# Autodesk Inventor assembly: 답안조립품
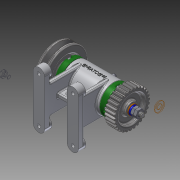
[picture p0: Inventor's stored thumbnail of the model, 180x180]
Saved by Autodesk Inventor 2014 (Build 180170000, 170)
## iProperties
Created: 2015-11
Part Number: 답안조립품
Document SubType Name: Assembly
Designer: Owner
Author: Owner
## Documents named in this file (16)
- C:\Documents and Settings\Owner\바탕 화면\451109V1002\451109V1002\답안조립품.iam
- C:\Documents and Settings\Owner\바탕 화면\451109V1002\451109V1002\본체.ipt
- C:\Documents and Settings\Owner\바탕 화면\451109V1002\451109V1002\축.ipt
- C:\Documents and Settings\Owner\바탕 화면\451109V1002\451109V1002\커버.ipt
- C:\Documents and Settings\Owner\바탕 화면\451109V1002\451109V1002\베어링 15 x 32 x 9.ipt
- C:\Documents and Settings\Owner\바탕 화면\451109V1002\451109V1002\오일 실 15 25 7.ipt
- C:\Documents and Settings\Owner\바탕 화면\451109V1002\451109V1002\V벨트풀리.ipt
- C:\Documents and Settings\Owner\바탕 화면\451109V1002\451109V1002\스퍼기어.ipt
- C:\Documents and Settings\Owner\바탕 화면\451109V1002\451109V1002\키 3 x 3 x 12.ipt
- C:\Documents and Settings\Owner\바탕 화면\451109V1002\451109V1002\볼트 M4 x 12.ipt
- C:\Documents and Settings\Owner\바탕 화면\451109V1002\451109V1002\너트 M 8.ipt
- C:\Documents and Settings\Owner\바탕 화면\451109V1002\451109V1002\스프링와셔 8.ipt
- C:\Documents and Settings\Owner\바탕 화면\451109V1002\451109V1002\와셔 8x17.ipt
- C:\Documents and Settings\Owner\바탕 화면\451109V1002\451109V1002\볼트 M 6 x 8.ipt
- C:\Documents and Settings\Owner\바탕 화면\451109V1002\451109V1002\와셔 6x11.5.ipt
- C:\Documents and Settings\Owner\바탕 화면\451109V1002\451109V1002\니플 M 6 x 0.75.ipt
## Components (11 placed, 3 different names)
1. KS B 2023 6002 - 15 x 32 x 9:1
2. KS B 2023 6002 - 15 x 32 x 9:2
3. V벨트풀리:1
4. ISO 4762 M4 x 12:1
5. ISO 4762 M4 x 12:2
6. ISO 4762 M4 x 12:3
7. ISO 4762 M4 x 12:4
8. ISO 4762 M4 x 12:5
9. ISO 4762 M4 x 12:6
10. ISO 4762 M4 x 12:7
11. ISO 4762 M4 x 12:8
